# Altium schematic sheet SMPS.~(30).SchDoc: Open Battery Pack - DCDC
size A3; Date: 26/03/2019; Author: Morgane Vallée - Samuel Lesueur; Revision: 1.0; SheetNumber: 2; SheetTotal: 5
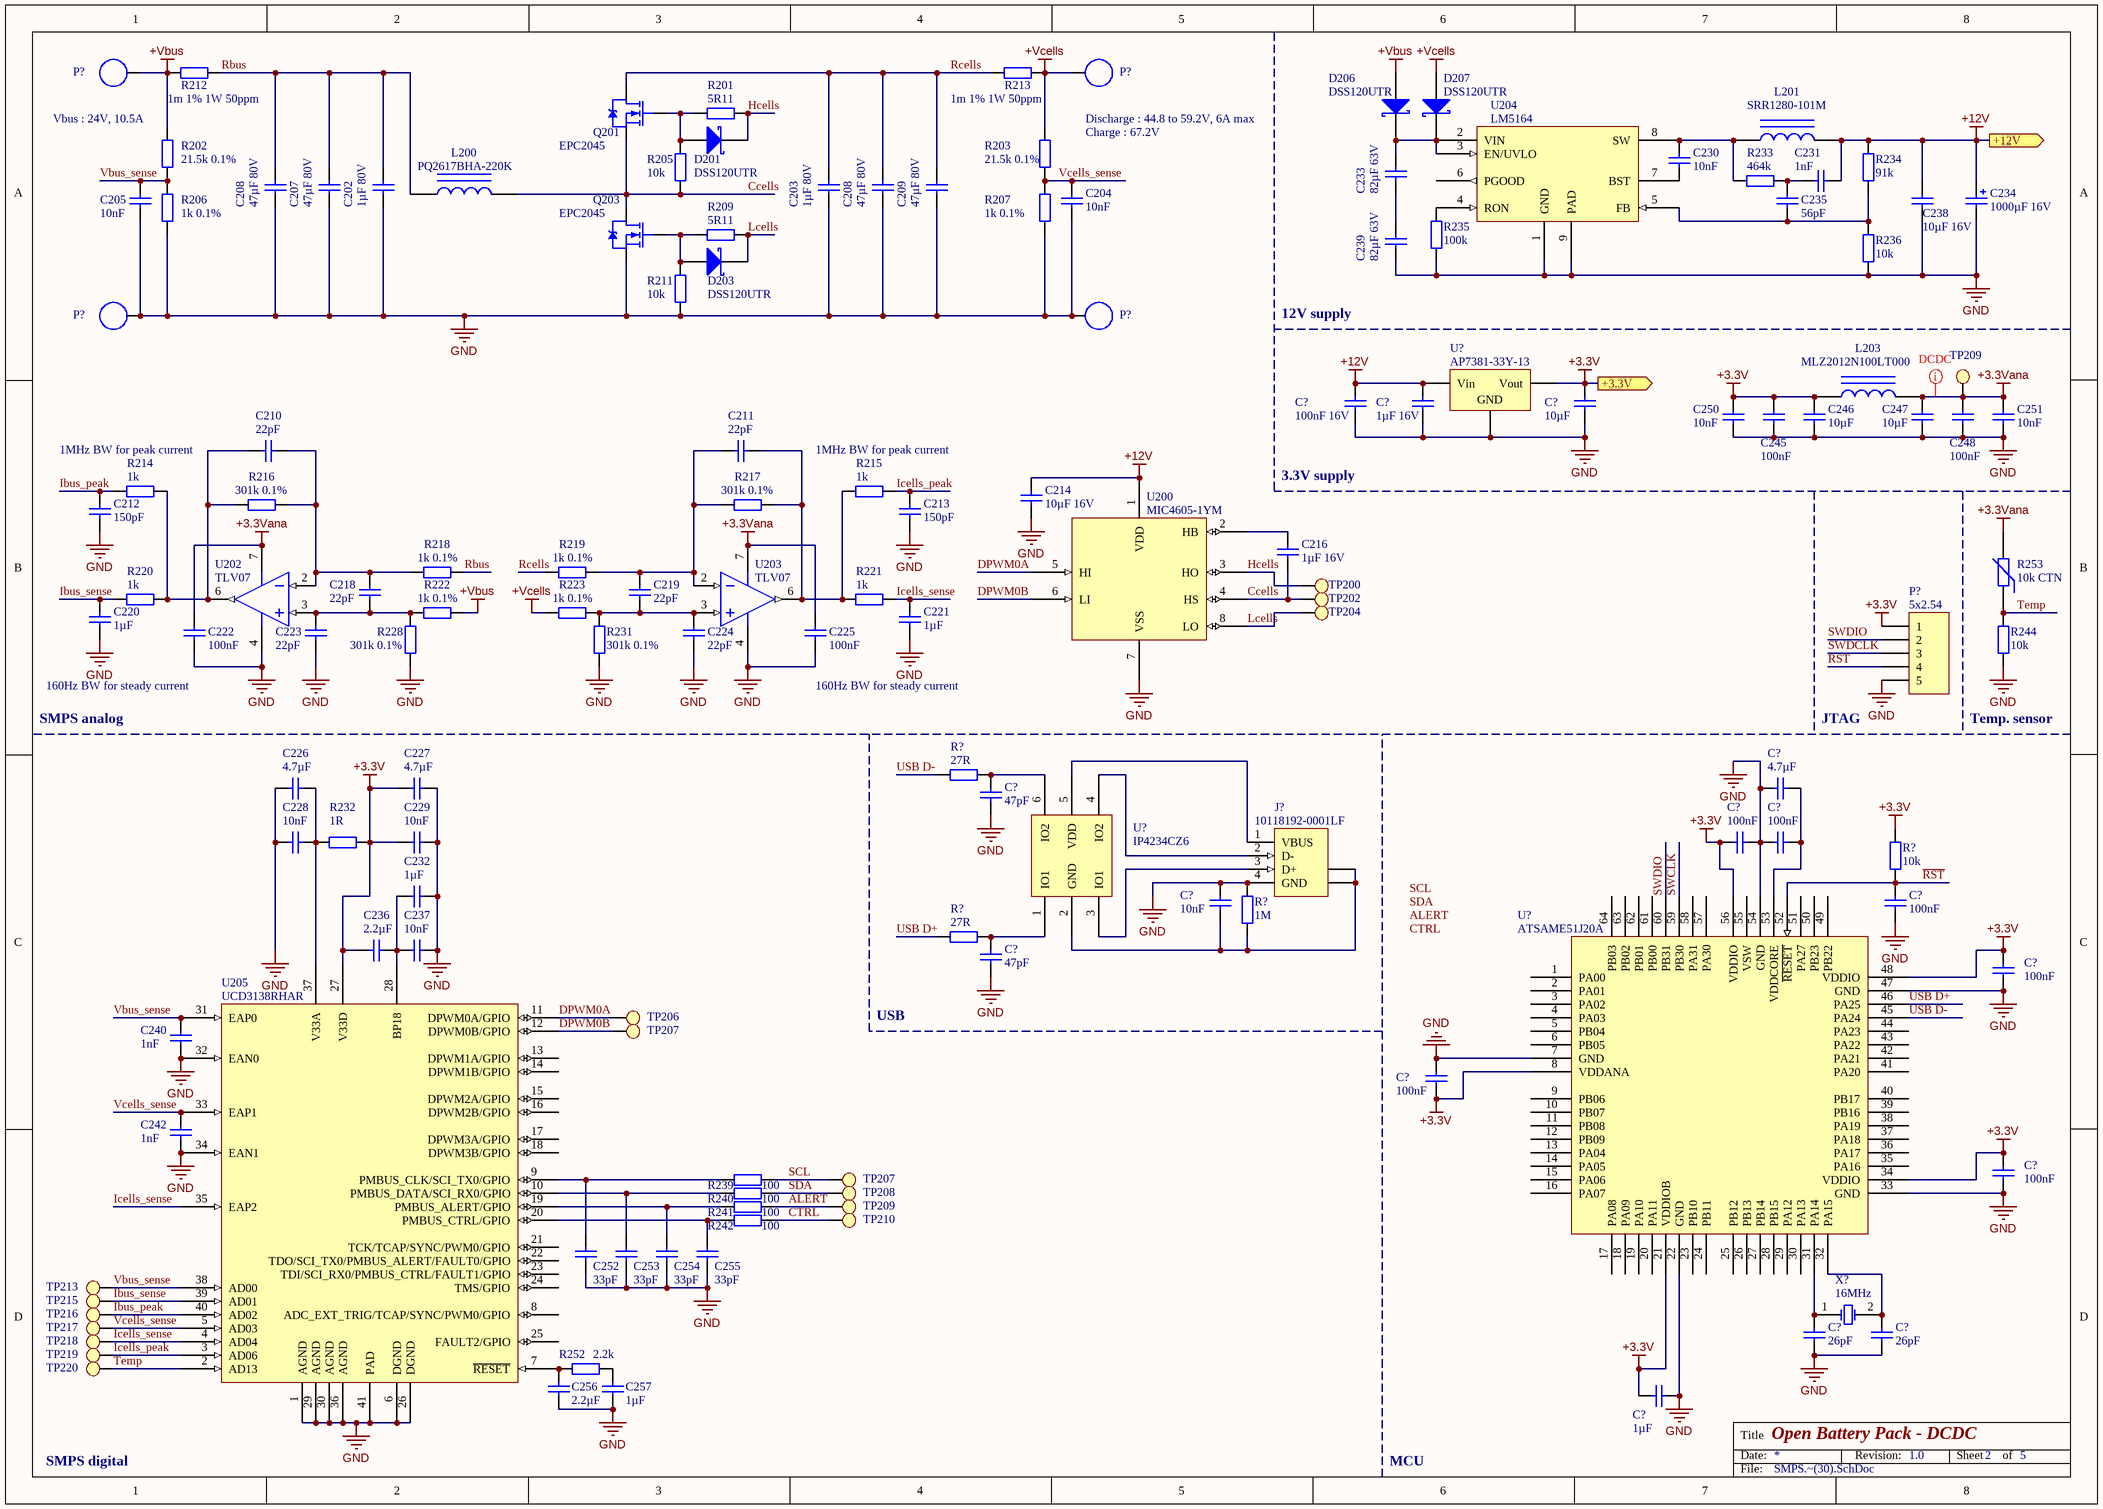
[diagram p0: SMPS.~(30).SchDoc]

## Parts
(Parts that share a designator on the sheet are numbered #1, #2 ... from top to bottom, then left to right.)
C202  1µF 80V  [CAP ALUM 10.3MM]
C203  1µF 80V  [CAP ALUM 10.3MM]
C204  10nF  [C0603]
C205  10nF  [C0603]
C207  47µF 80V  [CAP ALUM 10.3MM]
C208#1  47µF 80V  [CAP ALUM 10.3MM]
C208#2  47µF 80V  [CAP ALUM 10.3MM]
C209  47µF 80V  [CAP ALUM 10.3MM]
C210  22pF  [C0603]
C211  22pF  [C0603]
C212  150pF  [C0603]
C213  150pF  [C0603]
C214  10µF 16V  [C0805]
C216  1µF 16V  [C0603]
C218  22pF  [C0603]
C219  22pF  [C0603]
C220  1µF  [C0603]
C221  1µF  [C0603]
C222  100nF  [C0603]
C223  22pF  [C0603]
C224  22pF  [C0603]
C225  100nF  [C0603]
C226  4.7µF  [C0603]
C227  4.7µF  [C0603]
C228  10nF  [C0603]
C229  10nF  [C0603]
C230  10nF  [C0603]
C231  1nF  [C0603]
C232  1µF  [C0603]
C233  82µF 63V  [CAP ALUM 10.3MM]
C234  1000µF 16V  [CAP AL TH D10 L5 H17.5]
C235  56pF  [C0603]
C236  2.2µF  [C0603]
C237  10nF  [C0603]
C238  10µF 16V  [C0805]
C239  82µF 63V  [CAP ALUM 10.3MM]
C240  1nF  [C0603]
C242  1nF  [C0603]
C245  100nF  [C0603]
C246  10µF  [C0603]
C247  10µF  [C0603]
C248  100nF  [C0603]
C250  10nF  [C0603]
C251  10nF  [C0603]
C252  33pF  [C0603]
C253  33pF  [C0603]
C254  33pF  [C0603]
C255  33pF  [C0603]
C256  2.2µF  [C0603]
C257  1µF  [C0603]
C?#1  100nF 16V  [C0603]
C?#2  1µF 16V  [C0805]
C?#3  10µF  [C0603]
C?#4  47pF  [C0603]
C?#5  4.7µF  [C0603]
C?#6  100nF  [C0603]
C?#7  100nF  [C0603]
C?#8  10nF  [C0603]
C?#9  100nF  [C0603]
C?#10  47pF  [C0603]
C?#11  100nF  [C0603]
C?#12  100nF  [C0603]
C?#13  100nF  [C0603]
C?#14  26pF  [C0603]
C?#15  26pF  [C0603]
C?#16  1µF  [C0603]
D201  DSS120UTR  [SOD123F]
D203  DSS120UTR  [SOD123F]
D206  DSS120UTR  [SOD123F]
D207  DSS120UTR  [SOD123F]
J?  10118192-0001LF  [FCI USB 10118193-0001LF]
L200  PQ2617BHA-220K  [SELF_SMD_23.5x22]
L201  SRR1280-101M  [SELF_SMD_12.5x12.5]
L203  MLZ2012N100LT000  [C0805]
P?#1  PTH  [HOLE_4]  (value not drawn)
P?#2  PTH  [HOLE_4]  (value not drawn)
P?#3  PTH  [HOLE_4]  (value not drawn)
P?#4  PTH  [HOLE_4]  (value not drawn)
P?#5  5x2.54  [HDR1X5]
Q201  EPC2045  [TO220]
Q203  EPC2045  [TO220]
R201  5R11  [R0603]
R202  21.5k 0.1%  [R0603]
R203  21.5k 0.1%  [R0603]
R205  10k  [R0603]
R206  1k 0.1%  [R0603]
R207  1k 0.1%  [R0603]
R209  5R11  [R0603]
R211  10k  [R0603]
R212  1m 1% 1W 50ppm  [R1206]
R213  1m 1% 1W 50ppm  [R1206]
R214  1k  [R0603]
R215  1k  [R0603]
R216  301k 0.1%  [R0603]
R217  301k 0.1%  [R0603]
R218  1k 0.1%  [R0603]
R219  1k 0.1%  [R0603]
R220  1k  [R0603]
R221  1k  [R0603]
R222  1k 0.1%  [R0603]
R223  1k 0.1%  [R0603]
R228  301k 0.1%  [R0603]
R231  301k 0.1%  [R0603]
R232  1R  [R0603]
R233  464k  [R0603]
R234  91k  [R0603]
R235  100k  [R0603]
R236  10k  [R0603]
R239  100  [R0603]
R240  100  [R0603]
R241  100  [R0603]
R242  100  [R0603]
R244  10k  [R0603]
R252  2.2k  [R0603]
R253  10k CTN  [R0603]
R?#1  27R  [R0603]
R?#2  10k  [R0603]
R?#3  1M  [R0603]
R?#4  27R  [R0603]
TP200  Test Point  [Test Point]  (value not drawn)
TP202  Test Point  [Test Point]  (value not drawn)
TP204  Test Point  [Test Point]  (value not drawn)
TP206  Test Point  [Test Point]  (value not drawn)
TP207#1  Test Point  [Test Point]  (value not drawn)
TP207#2  Test Point  [Test Point]  (value not drawn)
TP208  Test Point  [Test Point]  (value not drawn)
TP209#1  Test Point  [Test Point]  (value not drawn)
TP209#2  Test Point  [Test Point]  (value not drawn)
TP210  Test Point  [Test Point]  (value not drawn)
TP213  Test Point  [Test Point]  (value not drawn)
TP215  Test Point  [Test Point]  (value not drawn)
TP216  Test Point  [Test Point]  (value not drawn)
TP217  Test Point  [Test Point]  (value not drawn)
TP218  Test Point  [Test Point]  (value not drawn)
TP219  Test Point  [Test Point]  (value not drawn)
TP220  Test Point  [Test Point]  (value not drawn)
U200  MIC4605-1YM  [SOIC-8]
U202  TLV07  [SOIC-8]
U203  TLV07  [SOIC-8]
U204  LM5164  [R-PDSO-G8]
U205  UCD3138RHAR  [S-PVQFN-N40]
U?#1  AP7381-33Y-13  [ST SOIC-8N]
U?#2  IP4234CZ6  [VISHAY TSOP-6 MO-193C]
U?#3  ATSAME51J20A  [TQFP-64N]
X?  16MHz  [ABRACON ABLS]

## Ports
+3.3V, +12V

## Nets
+3.3V: C227.1 C229.1 C236.2 C245.1 C246.1 C250.1 C?#3.1 C?#6.2 C?#11.2 C?#12.1 C?#13.2 C?#16.2 L203.1 P?#5.1 R232.1 R?#2.2 U205.27(V33D) U?#1.3(Vout) U?#3.8(VDDANA) U?#3.21(VDDIOB) U?#3.34(VDDIO) U?#3.48(VDDIO) U?#3.56(VDDIO) ; port +3.3V
+3.3Vana: C222.1 C225.1 C247.1 C248.1 C251.1 L203.2 R253.2 TP209#1.1 U202.7(V+) U203.7(V+)
+12V: C214.2 C231.2 C234.1 C238.1 C?#1.1 C?#2.1 L201.2 R234.1 U200.1(VDD) U?#1.1(Vin) ; port +12V
+Vbus: D206.1(A) P?#1.1 R202.1 R212.2 R222.1
+Vcells: D207.1(A) P?#2.1 R203.1 R213.1 R223.2
GND: C202.1 C203.1 C204.1 C205.1 C207.1 C208#1.1 C208#2.1 C209.1 C212.1 C213.1 C214.1 C220.1 C221.1 C222.2 C223.1 C224.1 C225.2 C226.1 C227.2 C228.1 C229.2 C232.1 C234.2 C237.1 C238.2 C239.2 C240.2 C242.2 C245.2 C246.2 C247.2 C248.2 C250.2 C251.2 C252.2 C253.2 C254.2 C255.2 C256.2 C257.2 C?#1.2 C?#2.2 C?#3.2 C?#4.1 C?#5.2 C?#6.1 C?#7.2 C?#8.2 C?#9.1 C?#10.1 C?#11.1 C?#12.2 C?#13.1 C?#14.1 C?#15.1 C?#16.1 J?.4(GND) P?#3.1 P?#4.1 P?#5.5 Q203.2(S) R206.2 R207.2 R211.2 R228.2 R231.2 R235.2 R236.2 R244.2 R?#3.1 U200.7(VSS) U202.4(V-) U203.4(V-) U204.1(GND) U204.9(PAD) U205.1(AGND) U205.6(DGND) U205.26(DGND) U205.29(AGND) U205.30(AGND) U205.32(EAN0) U205.34(EAN1) U205.36(AGND) U205.41(PAD) U?#1.2(GND) U?#3.7(GND) U?#3.22(GND) U?#3.33(GND) U?#3.47(GND) U?#3.54(GND)
ALERT: R241.2 TP209#2.1
Ccells: C216.1 L200.2 Q201.2(S) Q203.3(D) R205.2 TP202.1 U200.4(HS)
CTRL: R242.2 TP210.1
DPWM0A: TP206.1 U200.5(HI) U205.11(DPWM0A/GPIO)
DPWM0B: TP207#1.1 U200.6(LI) U205.12(DPWM0B/GPIO)
Hcells: D201.2(K) R201.1 TP200.1 U200.3(HO)
Ibus_peak: C212.2 R214.2 TP216.1 U205.40(AD02)
Ibus_sense: C220.2 R220.2 TP215.1 U205.39(AD01)
Icells_peak: C213.2 R215.1 TP219.1 U205.3(AD06)
Icells_sense: C221.2 R221.1 TP218.1 U205.4(AD04) U205.35(EAP2)
Lcells: D203.2(K) R209.1 TP204.1 U200.8(LO)
~{RST}: C?#9.2 P?#5.4 R?#2.1 U?#3.52(~{RESET})
Rbus: C202.2 C207.2 C208#1.2 L200.1 R212.1 R218.1
Rcells: C203.2 C208#2.2 C209.2 Q201.3(D) R213.2 R219.2
SCL: R239.2 TP207#2.1
SDA: R240.2 TP208.1
SWCLK: U?#3.59(PB30)
SWDCLK: P?#5.3
SWDIO: P?#5.2 U?#3.60(PB31)
Temp: R244.1 R253.1 TP220.1 U205.2(AD13)
USB D+: R?#4.1 U?#3.46(PA25)
USB D-: R?#1.1 U?#3.45(PA24)
Vbus_sense: C205.2 C240.1 R202.2 R206.1 TP213.1 U205.31(EAP0) U205.38(AD00)
Vcells_sense: C204.2 C242.1 R203.2 R207.1 TP217.1 U205.5(AD03) U205.33(EAP1)
NetC210_1: C210.1 R214.1 R216.2 R220.1 U202.6(OUT)
NetC210_2: C210.2 C218.2 R216.1 R218.2 U202.2(IN-)
NetC211_1: C211.1 C219.2 R217.2 R219.1 U203.2(IN-)
NetC211_2: C211.2 R215.2 R217.1 R221.2 U203.6(OUT)
NetC216_2: C216.2 U200.2(HB)
NetC218_1: C218.1 C223.2 R222.2 R228.1 U202.3(IN+)
NetC219_1: C219.1 C224.2 R223.1 R231.1 U203.3(IN+)
NetC226_2: C226.2 C228.2 R232.2 U205.37(V33A)
NetC230_1: C230.1 L201.1 R233.1 U204.8(SW)
NetC230_2: C230.2 U204.7(BST)
NetC231_1: C231.1 C235.2 R233.2
NetC232_2: C232.2 C236.1 C237.2 U205.28(BP18)
NetC233_1: C233.1 D206.2(K) D207.2(K) U204.2(VIN) U204.3(EN/UVLO)
NetC233_2: C233.2 C239.1
NetC235_1: C235.1 R234.2 R236.1 U204.5(FB)
NetC252_1: C252.1 R239.1 U205.9(PMBUS_CLK/SCI_TX0/GPIO)
NetC253_1: C253.1 R240.1 U205.10(PMBUS_DATA/SCI_RX0/GPIO)
NetC254_1: C254.1 R241.1 U205.19(PMBUS_ALERT/GPIO)
NetC255_1: C255.1 R242.1 U205.20(PMBUS_CTRL/GPIO)
NetC256_1: C256.1 R252.1 U205.7(~{RESET})
NetC257_1: C257.1 R252.2
NetC?#4_2: C?#4.2 R?#1.2 U?#2.6(IO2)
NetC?#5_1: C?#5.1 C?#7.1 U?#3.53(VDDCORE)
NetC?#8_1: C?#8.1 J?.5(SHLD) J?.6(SHLD) R?#3.2 U?#2.2(GND)
NetC?#10_2: C?#10.2 R?#4.2 U?#2.1(IO1)
NetC?#14_2: C?#14.2 U?#3.31(PA14) X?.1(OSC1)
NetC?#15_2: C?#15.2 U?#3.32(PA15) X?.2(OSC2)
NetD201_1: D201.1(A) Q201.1(G) R201.2 R205.1
NetD203_1: D203.1(A) Q203.1(G) R209.2 R211.1
NetJ?_1: J?.1(VBUS) U?#2.5(VDD)
NetJ?_2: J?.2(D-) U?#2.4(IO2)
NetJ?_3: J?.3(D+) U?#2.3(IO1)
NetR235_1: R235.1 U204.4(RON)

Not connected (* = marked no-connect by the designer): U204 6(PGOOD); U205 8(ADC_EXT_TRIG/TCAP/SYNC/PWM0/GPIO) 13(DPWM1A/GPIO) 14(DPWM1B/GPIO) 15(DPWM2A/GPIO) 16(DPWM2B/GPIO) 17(DPWM3A/GPIO) 18(DPWM3B/GPIO) 21(TCK/TCAP/SYNC/PWM0/GPIO) 22(TDO/SCI_TX0/PMBUS_ALERT/FAULT0/GPIO) 23(TDI/SCI_RX0/PMBUS_CTRL/FAULT1/GPIO) 24(TMS/GPIO) 25(FAULT2/GPIO); U?#3 1(PA00) 2(PA01) 3(PA02) 4(PA03) 5(PB04) 6(PB05) 9(PB06) 10(PB07) 11(PB08) 12(PB09) 13(PA04) 14(PA05) 15(PA06) 16(PA07) 17(PA08) 18(PA09) 19(PA10) 20(PA11) 23(PB10) 24(PB11) 25(PB12) 26(PB13) 27(PB14) 28(PB15) 29(PA12) 30(PA13) 35(PA16) 36(PA17) 37(PA18) 38(PA19) 39(PB16) 40(PB17) 41(PA20) 42(PA21) 43(PA22) 44(PA23) 49(PB22) 50(PB23) 51(PA27) 55(VSW) 57(PA30) 58(PA31) 61(PB00) 62(PB01) 63(PB02) 64(PB03)

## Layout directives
net class DCDC: +3.3Vana

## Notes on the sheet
- (near R202) Vbus : 24V, 10.5A
- Discharge : 44.8 to 59.2V, 6A max
- Charge : 67.2V
- 12V supply
- 1MHz BW for peak current
- 3.3V supply
- SMPS analog
- 160Hz BW for steady current
- JTAG
- Temp. sensor
- USB
- SMPS digital
- MCU
- Labels drawn without touching a wire or pin: ALERT, CTRL, SCL, SDA

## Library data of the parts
C202-C205 C207 C208#1 C208#2 C209-C214 C216 C218-C233 C235-C240 C242 C245-C248 C250-C257 C?#1-C?#16 = Cap: Capacitor
C234 = Cap Pol1: Polarized Capacitor (Radial)
D201 D203 D206 D207 = D Schottky: Schottky Diode; pin to pad: 1>1+3
J? = 1-353576-1: USB 1.1, Right Angle, SMT, A Type, Receptacle, 4 Position, White; pin to pad: 4>5 5>S 6>S
L200 L201 L203 = Inductor Iron: Magnetic-Core Inductor
P?#1-P?#4 = PTH: Plated Trough Hole for screew
P?#5 = Header 5: Header, 5-Pin
Q201 Q203 = MOSFET_N
R201-R203 R205-R207 R209 R211-R223 R228 R231-R236 R239-R242 R244 R252 R?#1-R?#4 = Res2: Resistor
R253 = Res Varistor: Varistor (Voltage-Sensitive Resistor)
U200 = MIC4605-1YM: 85V Half-Bridge MOSFET Driver with Adaptive Dead Time  and Shoot-Through Protection
U202 U203 = TLV07: 36-V Precision,Rail-to-RailOutputOperationalAmplifier
U204 = LM5164: 100-V Input, 1-A synchronous buck DC/DC converter with ultra-low IQ
U205 = UCD3138RHAR: Highly Integrated Digital Controller for Isolated Power with 3 Feedback Loops and 8 DPWM Outputs, 40pins
U?#1 = Volt Reg: Voltage Regulator; pin to pad: 1>8 2>2+3+6+7 3>1
U?#2 = IP4234CZ6: Single USB 2.0 ESD protection to IEC 61000-4-2 level 4
X? = XTAL: Crystal Oscillator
